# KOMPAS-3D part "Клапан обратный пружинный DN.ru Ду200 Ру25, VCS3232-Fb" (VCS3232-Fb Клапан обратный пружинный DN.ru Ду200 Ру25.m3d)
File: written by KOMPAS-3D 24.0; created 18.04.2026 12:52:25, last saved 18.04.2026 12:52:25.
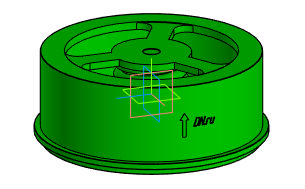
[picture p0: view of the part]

Document properties: Автор: 712; Полное имя файла: C:\Users\712\Desktop\Новая папка (4)\VCS3232-Fb Клапан обратный пружинный DN.ru Ду200 Ру25.m3d

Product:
- Component: Пружина 1086-1155 ГОСТ 18793-80  | qty 1  | additional columns: 3953604318-4147491677-0; Деталь; Пользователь Windows; c; Шероховатость не задана; Да; Сталь 10  ГОСТ 1050-88; source file: Деталь_3.m3d
- Body: Тело 1  | qty 1
    Масса: 13.506002
- Part/product: Клапан обратный пружинный DN.ru Ду200 Ру25  | designation VCS3232-Fb
    Масса: 9.5
    Раздел спецификации: Прочие изделия
    Примечание: D100-04003
    additional columns: 071bd168-1a06-425c-849c-e99e84a96128; Деталь; 712; c; Шероховатость не задана; Да

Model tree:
1. Операция без истории:2

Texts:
  VCS3232-Fb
